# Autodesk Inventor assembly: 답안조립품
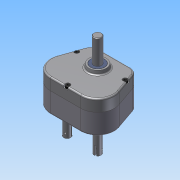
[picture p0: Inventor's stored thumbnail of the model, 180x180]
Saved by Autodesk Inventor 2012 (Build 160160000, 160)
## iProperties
Created: 2014-12
Part Number: 답안조립품
Document SubType Name: Assembly
Designer: User11
Author: User11
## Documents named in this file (14)
- C:\Users\User11\Desktop\441208V1031\답안조립품.iam
- C:\Users\User11\Desktop\441208V1031\본체.ipt
- C:\Users\User11\Desktop\441208V1031\오일시일-D-15.ipt
- C:\Users\User11\Desktop\441208V1031\베어링- 6202.ipt
- C:\Users\User11\Desktop\441208V1031\커버.ipt
- C:\Users\User11\Desktop\441208V1031\베어링- 6203.ipt
- C:\Users\User11\Desktop\441208V1031\서브축.ipt
- C:\Users\User11\Desktop\441208V1031\메인축.ipt
- C:\Users\User11\Desktop\441208V1031\오일시일-D-17.ipt
- C:\Users\User11\Desktop\441208V1031\키5x5.ipt
- C:\Users\User11\Desktop\441208V1031\메인기어.ipt
- C:\Users\User11\Desktop\441208V1031\멈춤링.ipt
- C:\Users\User11\Desktop\441208V1031\서브기어.ipt
- C:\Users\User11\Desktop\441208V1031\M 5 x 35.ipt
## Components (15 placed, 6 different names)
1. KS B 2804 D D - 15 30 7:1
2. KS B 2804 D D - 15 30 7:2
3. KS B 2023 6202 - 15 x 35 x 11:1
4. KS B 2023 6202 - 15 x 35 x 11:2
5. KS B 2023 6203 - 17 x 40 x 12:1
6. KS B 2023 6203 - 17 x 40 x 12:2
7. KS B 2023 6203 - 17 x 40 x 12:3
8. KS B 2023 6203 - 17 x 40 x 12:4
9. KS B 2804 D D - 17 30 8:1
10. KS B 1336 17 x 1:1
11. KS B 1336 17 x 1:2
12. KS B 1336 17 x 1:3
13. KS B 1003 - 미터 M 5 x 35:1
14. KS B 1003 - 미터 M 5 x 35:2
15. KS B 1003 - 미터 M 5 x 35:3
